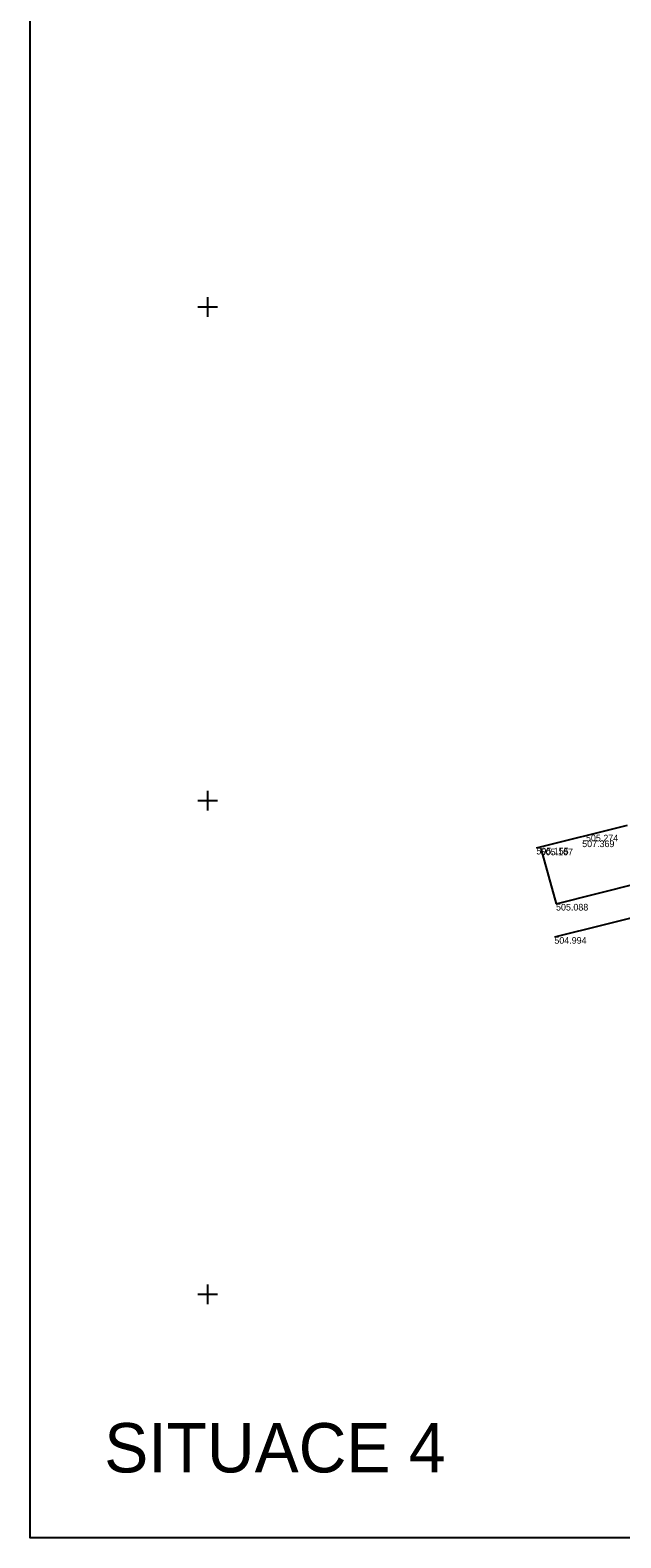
# Model space of a CAD drawing. Extents: x -669750 to -669514, y -1130590 to -1130196.
# Drawn here: x -669747.2 to -669723.3, y -1130589.9 to -1130528.8 of the extents above; entities that cross this region are included whole.
import ezdxf

# ---------------------------------------------------------------- set-up
doc = ezdxf.new("R2010")
doc.units = 0
for name, color, linetype in [('Vrstva 1', 7, 'Continuous'), ('Vrstva 4', 7, 'Continuous'), ('Vrstva 61', 7, 'Continuous'), ('Vrstva 62', 7, 'Continuous'), ('Vrstva 63', 7, 'Continuous'), ('Vrstva 7', 7, 'Continuous'), ('Vrstva 8', 7, 'Continuous')]:
    doc.layers.add(name, color=color, linetype=linetype)

# ---------------------------------------------------------------- blocks, each defined once
blk = doc.blocks.new('SC2406')
at = {"layer": 'Vrstva 1'}
blk.add_line((0, 0), (0, 0), dxfattribs=at)

msp = doc.modelspace()

# ---------------------------------------------------------------- linework, layer by layer
at = {"layer": 'Vrstva 62'}
for p, q in [((-669739.6, -1130540), (-669740.4, -1130540)), ((-669740, -1130539.6), (-669740, -1130540.4)), ((-669740, -1130559.6), (-669740, -1130560.4)), ((-669739.6, -1130560), (-669740.4, -1130560)), ((-669740, -1130579.6), (-669740, -1130580.4)), ((-669739.6, -1130580), (-669740.4, -1130580))]:
    msp.add_line(p, q, dxfattribs=at)
at = {"layer": 'Vrstva 63'}
msp.add_lwpolyline([(-669747.186, -1130471.064), (-669579.186, -1130471.064), (-669579.186, -1130589.864), (-669747.186, -1130589.864)], close=True, dxfattribs=at)
at = {"layer": 'Vrstva 7'}
for p, q in [((-669726.509, -1130561.94295), (-669725.889, -1130564.17995)), ((-669715.508, -1130562.93195), (-669725.957, -1130565.52495)), ((-669725.889, -1130564.17995), (-669722.563, -1130563.34395))]:
    msp.add_line(p, q, dxfattribs=at)
at = {"layer": 'Vrstva 8'}
msp.add_line((-669726.685, -1130561.90795), (-669722.999, -1130560.99295), dxfattribs=at)

# ---------------------------------------------------------------- block references
at = {"layer": 'Vrstva 1', "xscale": 0.1, "yscale": 0.10000000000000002}
for p in [(-669724.677, -1130561.379), (-669726.685, -1130561.908), (-669726.509, -1130561.943), (-669724.83, -1130561.611), (-669725.889, -1130564.18), (-669725.957, -1130565.525)]:
    msp.add_blockref('SC2406', p, dxfattribs=at)

# ---------------------------------------------------------------- texts
at = {"layer": 'Vrstva 4'}
for s, p in [('505.274', (-669724.677, -1130561.649)), ('505.155', (-669726.685, -1130562.178)), ('505.167', (-669726.509, -1130562.213)), ('507.369', (-669724.83, -1130561.881)), ('505.088', (-669725.889, -1130564.45)), ('504.994', (-669725.957, -1130565.795))]:
    msp.add_text(s, height=0.27, dxfattribs=at).set_placement(p)
at = {"layer": 'Vrstva 61'}
msp.add_text('SITUACE 4', height=1.999998, dxfattribs=at).set_placement((-669744.187, -1130587.215))

doc.saveas('drawing.dxf')
